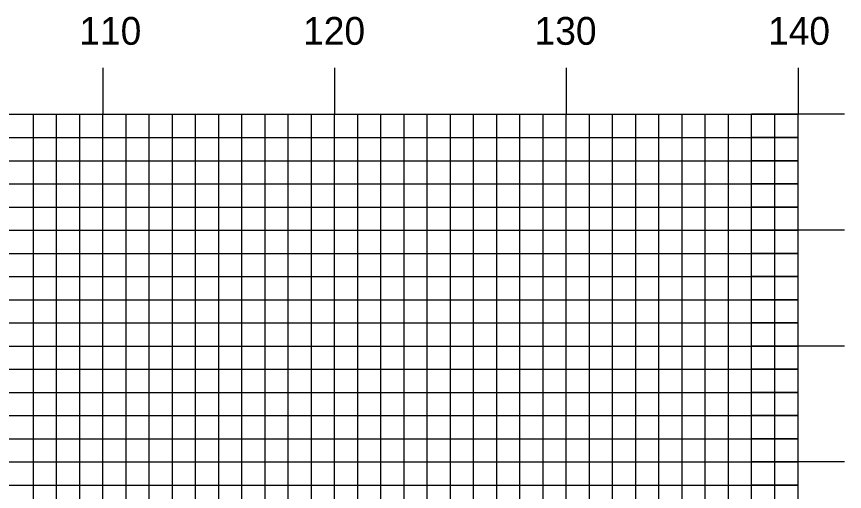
# Model space of a CAD drawing. Extents: x 1760610 to 1760954, y 442591 to 442811.
# Drawn here: x 1760882.49 to 1760918.22, y 442682.39 to 442702.88 of the extents above; entities that cross this region are included whole.
import ezdxf

# ---------------------------------------------------------------- set-up
doc = ezdxf.new("R2010")
doc.units = 0
for name, color, linetype in [('H_V ANNOTATION', 7, 'Continuous'), ('MAJOR', 7, 'Continuous'), ('MINOR', 7, 'Continuous')]:
    doc.layers.add(name, color=color, linetype=linetype)

msp = doc.modelspace()

# ---------------------------------------------------------------- linework, layer by layer
at = {"layer": 'MAJOR'}
for p, q in [((1760886.214, 442700.669), (1760886.214, 442698.665)), ((1760896.214, 442700.669), (1760896.214, 442698.665)), ((1760906.214, 442700.669), (1760906.214, 442698.665)), ((1760916.214, 442700.669), (1760916.214, 442698.665)), ((1760636.214, 442698.665), (1760916.214, 442698.665)), ((1760636.214, 442698.665), (1760916.214, 442698.665)), ((1760886.214, 442663.665), (1760886.214, 442698.665)), ((1760896.214, 442663.665), (1760896.214, 442698.665)), ((1760906.214, 442663.665), (1760906.214, 442698.665)), ((1760918.218, 442698.665), (1760914.21, 442698.665)), ((1760916.214, 442663.665), (1760916.214, 442698.665)), ((1760916.214, 442663.665), (1760916.214, 442698.665)), ((1760636.214, 442693.665), (1760916.214, 442693.665)), ((1760918.218, 442693.665), (1760914.21, 442693.665)), ((1760636.214, 442688.665), (1760916.214, 442688.665)), ((1760918.218, 442688.665), (1760914.21, 442688.665)), ((1760636.214, 442683.665), (1760916.214, 442683.665)), ((1760918.218, 442683.665), (1760914.21, 442683.665))]:
    msp.add_line(p, q, dxfattribs=at)
at = {"layer": 'MINOR'}
for p, q in [((1760883.214, 442663.665), (1760883.214, 442698.665)), ((1760884.214, 442663.665), (1760884.214, 442698.665)), ((1760885.214, 442663.665), (1760885.214, 442698.665)), ((1760887.214, 442663.665), (1760887.214, 442698.665)), ((1760888.214, 442663.665), (1760888.214, 442698.665)), ((1760889.214, 442663.665), (1760889.214, 442698.665)), ((1760890.214, 442663.665), (1760890.214, 442698.665)), ((1760891.214, 442663.665), (1760891.214, 442698.665)), ((1760892.214, 442663.665), (1760892.214, 442698.665)), ((1760893.214, 442663.665), (1760893.214, 442698.665)), ((1760894.214, 442663.665), (1760894.214, 442698.665)), ((1760895.214, 442663.665), (1760895.214, 442698.665)), ((1760897.214, 442663.665), (1760897.214, 442698.665)), ((1760898.214, 442663.665), (1760898.214, 442698.665)), ((1760899.214, 442663.665), (1760899.214, 442698.665)), ((1760900.214, 442663.665), (1760900.214, 442698.665)), ((1760901.214, 442663.665), (1760901.214, 442698.665)), ((1760902.214, 442663.665), (1760902.214, 442698.665)), ((1760903.214, 442663.665), (1760903.214, 442698.665)), ((1760904.214, 442663.665), (1760904.214, 442698.665)), ((1760905.214, 442663.665), (1760905.214, 442698.665)), ((1760907.214, 442663.665), (1760907.214, 442698.665)), ((1760908.214, 442663.665), (1760908.214, 442698.665)), ((1760909.214, 442663.665), (1760909.214, 442698.665)), ((1760910.214, 442663.665), (1760910.214, 442698.665)), ((1760911.214, 442663.665), (1760911.214, 442698.665)), ((1760912.214, 442663.665), (1760912.214, 442698.665)), ((1760913.214, 442663.665), (1760913.214, 442698.665)), ((1760914.214, 442663.665), (1760914.214, 442698.665)), ((1760915.214, 442663.665), (1760915.214, 442698.665)), ((1760636.214, 442697.665), (1760916.214, 442697.665)), ((1760916.214, 442697.665), (1760914.21, 442697.665)), ((1760636.214, 442696.665), (1760916.214, 442696.665)), ((1760916.214, 442696.665), (1760914.21, 442696.665)), ((1760636.214, 442695.665), (1760916.214, 442695.665)), ((1760916.214, 442695.665), (1760914.21, 442695.665)), ((1760636.214, 442694.665), (1760916.214, 442694.665)), ((1760916.214, 442694.665), (1760914.21, 442694.665)), ((1760636.214, 442692.665), (1760916.214, 442692.665)), ((1760916.214, 442692.665), (1760914.21, 442692.665)), ((1760636.214, 442691.665), (1760916.214, 442691.665)), ((1760916.214, 442691.665), (1760914.21, 442691.665)), ((1760636.214, 442690.665), (1760916.214, 442690.665)), ((1760916.214, 442690.665), (1760914.21, 442690.665)), ((1760636.214, 442689.665), (1760916.214, 442689.665)), ((1760916.214, 442689.665), (1760914.21, 442689.665)), ((1760636.214, 442687.665), (1760916.214, 442687.665)), ((1760916.214, 442687.665), (1760914.21, 442687.665)), ((1760636.214, 442686.665), (1760916.214, 442686.665)), ((1760916.214, 442686.665), (1760914.21, 442686.665)), ((1760636.214, 442685.665), (1760916.214, 442685.665)), ((1760916.214, 442685.665), (1760914.21, 442685.665)), ((1760636.214, 442684.665), (1760916.214, 442684.665)), ((1760916.214, 442684.665), (1760914.21, 442684.665)), ((1760636.214, 442682.665), (1760916.214, 442682.665)), ((1760916.214, 442682.665), (1760914.21, 442682.665))]:
    msp.add_line(p, q, dxfattribs=at)

# ---------------------------------------------------------------- texts
at = {"layer": 'H_V ANNOTATION'}
for s, p in [('110', (1760885.197, 442701.665)), ('120', (1760894.854, 442701.665)), ('130', (1760904.844, 442701.665)), ('140', (1760914.919, 442701.665))]:
    msp.add_text(s, height=1.2, dxfattribs=at).set_placement(p)

doc.saveas('drawing.dxf')
